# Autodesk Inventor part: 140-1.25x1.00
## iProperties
Created: 2007-06
Part Number: 140-1.25x1.00
Document SubType Name: Modeling
Designer: btaylor
Density: 1 g/cm^3
Author: btaylor
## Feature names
1. Extrusion1
2. Extrusion2
3. Extrusion3
4. Chamfer1
5. Extrusion4
6. Fillet1
7. Fillet2
8. Chamfer2
